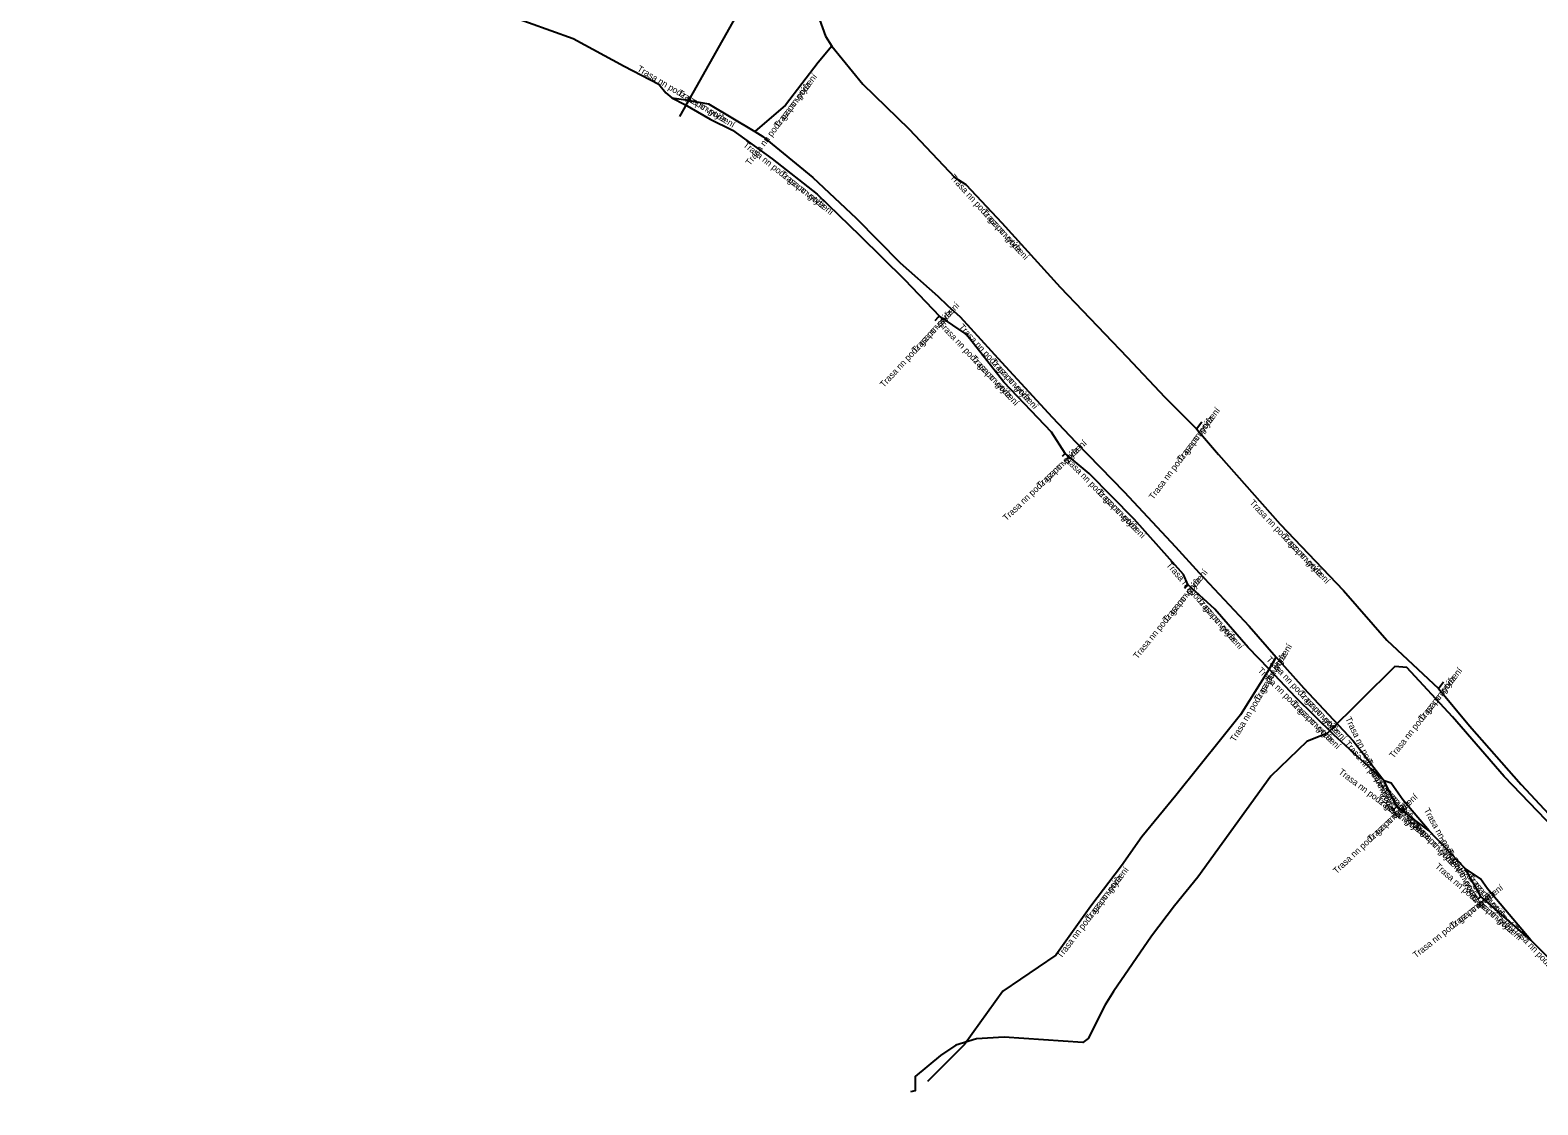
# Model space of a CAD drawing. Extents: x -703240 to -702678, y -1007635 to -1007322.
# Drawn here: x -703170.5 to -703052.5, y -1007557.6 to -1007473.5 of the extents above; entities that cross this region are included whole.
import ezdxf

# ---------------------------------------------------------------- set-up
doc = ezdxf.new("R2010")
doc.units = 0
for name, color, linetype in [('Popiskový text - Ostatní atributy Trasy', 7, 'Continuous'), ('Spojnice NN', 7, 'Continuous'), ('Spojnice VN', 7, 'Continuous')]:
    doc.layers.add(name, color=color, linetype=linetype)

msp = doc.modelspace()

# ---------------------------------------------------------------- linework, layer by layer
at = {"layer": 'Spojnice NN'}
for points in [[(-703105.19, -1007457.24), (-703106.16, -1007459.83), (-703107.31, -1007462.78), (-703109.11, -1007466.66), (-703109.74, -1007469.54), (-703109.29, -1007470.92), (-703108.22, -1007473.93), (-703107.73, -1007474.7)], [(-703105.19, -1007457.24), (-703106.16, -1007459.83), (-703107.31, -1007462.78), (-703109.11, -1007466.66), (-703109.74, -1007469.54), (-703109.29, -1007470.92), (-703108.22, -1007473.93), (-703107.73, -1007474.7)], [(-703170.48, -1007458.83), (-703167.59, -1007459.63), (-703164.52, -1007460.71), (-703160.1, -1007462.3), (-703155.58, -1007463.8), (-703150.53, -1007465.57), (-703146.69, -1007466.98), (-703141.78, -1007469.02), (-703136.93, -1007470.9), (-703131.46, -1007472.86), (-703127.97, -1007474.1), (-703123.99, -1007476.28), (-703121.27, -1007477.68), (-703120.71, -1007478.36), (-703120.24, -1007478.76)], [(-703170.48, -1007458.83), (-703167.59, -1007459.63), (-703164.52, -1007460.71), (-703160.1, -1007462.3), (-703155.58, -1007463.8), (-703150.53, -1007465.57), (-703146.69, -1007466.98), (-703141.78, -1007469.02), (-703136.93, -1007470.9), (-703131.46, -1007472.86), (-703127.97, -1007474.1), (-703123.99, -1007476.28), (-703121.27, -1007477.68), (-703120.71, -1007478.36), (-703120.24, -1007478.76)], [(-703107.73, -1007474.7), (-703108.8, -1007475.97), (-703111.34, -1007479.33), (-703113.75, -1007481.39)], [(-703107.73, -1007474.7), (-703108.8, -1007475.97), (-703111.34, -1007479.33), (-703113.75, -1007481.39)], [(-703107.73, -1007474.7), (-703105.3, -1007477.69), (-703101.7, -1007481.18), (-703098.1, -1007484.98), (-703097.23, -1007485.53), (-703094.43, -1007488.53), (-703089.86, -1007493.56), (-703084.61, -1007499.04), (-703081.67, -1007502.19), (-703079.19, -1007504.66)], [(-703107.73, -1007474.7), (-703105.3, -1007477.69), (-703101.7, -1007481.18), (-703098.1, -1007484.98), (-703097.23, -1007485.53), (-703094.43, -1007488.53), (-703089.86, -1007493.56), (-703084.61, -1007499.04), (-703081.67, -1007502.19), (-703079.19, -1007504.66)], [(-703120.24, -1007478.76), (-703119.33, -1007478.88), (-703117.38, -1007479.22), (-703113.75, -1007481.39)], [(-703120.24, -1007478.76), (-703119.24, -1007479.28), (-703117.25, -1007480.43), (-703115.5, -1007481.27), (-703112.39, -1007483.52), (-703108.87, -1007486.3), (-703105.53, -1007489.53), (-703102.01, -1007493), (-703099.3, -1007495.83)], [(-703120.24, -1007478.76), (-703119.33, -1007478.88), (-703117.38, -1007479.22), (-703113.75, -1007481.39)], [(-703120.24, -1007478.76), (-703119.24, -1007479.28), (-703117.25, -1007480.43), (-703115.5, -1007481.27), (-703112.39, -1007483.52), (-703108.87, -1007486.3), (-703105.53, -1007489.53), (-703102.01, -1007493), (-703099.3, -1007495.83)], [(-703113.75, -1007481.39), (-703113.13, -1007481.77), (-703109.22, -1007484.98), (-703105.81, -1007488.17), (-703102.37, -1007491.67), (-703099.42, -1007494.27), (-703098.67, -1007495), (-703097.68, -1007495.9), (-703094.44, -1007499.44), (-703090.48, -1007503.74), (-703088.62, -1007505.7), (-703084.85, -1007509.58), (-703080.82, -1007513.88), (-703078.98, -1007515.94), (-703075.05, -1007520.11), (-703072.95, -1007522.53)], [(-703113.75, -1007481.39), (-703113.13, -1007481.77), (-703109.22, -1007484.98), (-703105.81, -1007488.17), (-703102.37, -1007491.67), (-703099.42, -1007494.27), (-703098.67, -1007495), (-703097.68, -1007495.9), (-703094.44, -1007499.44), (-703090.48, -1007503.74), (-703088.62, -1007505.7), (-703084.85, -1007509.58), (-703080.82, -1007513.88), (-703078.98, -1007515.94), (-703075.05, -1007520.11), (-703072.95, -1007522.53)], [(-703099.3, -1007495.83), (-703099.4, -1007495.92), (-703099.66, -1007496.2)], [(-703099.3, -1007495.83), (-703099.4, -1007495.92), (-703099.66, -1007496.2)], [(-703089.46, -1007506.59), (-703090.54, -1007504.93), (-703094.25, -1007501.01), (-703097.2, -1007497.24), (-703099.3, -1007495.83)], [(-703089.46, -1007506.59), (-703090.54, -1007504.93), (-703094.25, -1007501.01), (-703097.2, -1007497.24), (-703099.3, -1007495.83)], [(-703079.19, -1007504.66), (-703078.77, -1007504.1)], [(-703079.19, -1007504.66), (-703078.77, -1007504.1)], [(-703079.19, -1007504.66), (-703077.45, -1007506.67), (-703072.62, -1007512.11), (-703067.67, -1007517.31), (-703064.27, -1007521.2), (-703060.24, -1007524.97)], [(-703079.19, -1007504.66), (-703077.45, -1007506.67), (-703072.62, -1007512.11), (-703067.67, -1007517.31), (-703064.27, -1007521.2), (-703060.24, -1007524.97)], [(-703089.46, -1007506.59), (-703089.7, -1007506.82)], [(-703089.46, -1007506.59), (-703089.7, -1007506.82)], [(-703079.87, -1007516.84), (-703080.2, -1007516.06), (-703084.05, -1007511.74), (-703087.58, -1007508.16), (-703089.46, -1007506.59)], [(-703079.87, -1007516.84), (-703080.2, -1007516.06), (-703084.05, -1007511.74), (-703087.58, -1007508.16), (-703089.46, -1007506.59)], [(-703079.87, -1007516.84), (-703080.13, -1007517.16)], [(-703079.87, -1007516.84), (-703080.13, -1007517.16)], [(-703073.5, -1007523.46), (-703075.14, -1007521.78), (-703077.75, -1007518.77), (-703079.87, -1007516.84)], [(-703073.5, -1007523.46), (-703075.14, -1007521.78), (-703077.75, -1007518.77), (-703079.87, -1007516.84)], [(-703073.5, -1007523.46), (-703072.95, -1007522.53)], [(-703073.5, -1007523.46), (-703072.95, -1007522.53)], [(-703072.95, -1007522.53), (-703070.78, -1007524.95), (-703066.91, -1007529.07), (-703064.48, -1007532.21)], [(-703072.95, -1007522.53), (-703070.78, -1007524.95), (-703066.91, -1007529.07), (-703064.48, -1007532.21)], [(-703073.5, -1007523.46), (-703075.73, -1007527.03), (-703077.2, -1007528.88), (-703080.81, -1007533.35), (-703083.45, -1007536.6), (-703085.05, -1007538.87), (-703087.44, -1007542.01), (-703090.19, -1007545.86), (-703094.33, -1007548.68), (-703097.35, -1007552.84), (-703100.24, -1007555.74)], [(-703073.5, -1007523.46), (-703075.73, -1007527.03), (-703077.2, -1007528.88), (-703080.81, -1007533.35), (-703083.45, -1007536.6), (-703085.05, -1007538.87), (-703087.44, -1007542.01), (-703090.19, -1007545.86), (-703094.33, -1007548.68), (-703097.35, -1007552.84), (-703100.24, -1007555.74)], [(-703064.48, -1007532.21), (-703068.44, -1007528.61), (-703071.41, -1007525.68), (-703073.5, -1007523.46)], [(-703064.48, -1007532.21), (-703068.44, -1007528.61), (-703071.41, -1007525.68), (-703073.5, -1007523.46)], [(-703060.24, -1007524.97), (-703059.84, -1007524.46)], [(-703060.24, -1007524.97), (-703059.84, -1007524.46)], [(-703060.24, -1007524.97), (-703057.82, -1007527.9), (-703053.76, -1007532.5), (-703049.79, -1007536.76), (-703045.88, -1007540.85), (-703042.43, -1007544.47), (-703037.97, -1007549.38), (-703033.75, -1007553.9), (-703030.23, -1007557.57)], [(-703060.24, -1007524.97), (-703057.82, -1007527.9), (-703053.76, -1007532.5), (-703049.79, -1007536.76), (-703045.88, -1007540.85), (-703042.43, -1007544.47), (-703037.97, -1007549.38), (-703033.75, -1007553.9), (-703030.23, -1007557.57)], [(-703060.96, -1007536.12), (-703063.03, -1007533.7), (-703063.95, -1007532.39), (-703064.48, -1007532.21)], [(-703063.51, -1007534.22), (-703064.48, -1007532.21)], [(-703063.51, -1007534.22), (-703064.48, -1007532.21)], [(-703060.96, -1007536.12), (-703063.03, -1007533.7), (-703063.95, -1007532.39), (-703064.48, -1007532.21)], [(-703063.51, -1007534.22), (-703063.84, -1007534.53)], [(-703063.51, -1007534.22), (-703063.84, -1007534.53)], [(-703060.96, -1007536.12), (-703063.51, -1007534.22)], [(-703060.96, -1007536.12), (-703063.51, -1007534.22)], [(-703058.14, -1007539.07), (-703060.96, -1007536.12)], [(-703058.14, -1007539.07), (-703060.96, -1007536.12)], [(-703053.01, -1007544.68), (-703056.39, -1007540.67), (-703056.95, -1007539.89), (-703058.14, -1007539.07)], [(-703056.93, -1007541.26), (-703058.14, -1007539.07)], [(-703056.93, -1007541.26), (-703058.14, -1007539.07)], [(-703053.01, -1007544.68), (-703056.39, -1007540.67), (-703056.95, -1007539.89), (-703058.14, -1007539.07)], [(-703056.93, -1007541.26), (-703057.17, -1007541.45)], [(-703056.93, -1007541.26), (-703057.17, -1007541.45)], [(-703053.01, -1007544.68), (-703056.93, -1007541.26)], [(-703053.01, -1007544.68), (-703056.93, -1007541.26)], [(-703045.83, -1007551.96), (-703046.67, -1007551.19), (-703050.31, -1007547.33), (-703053.01, -1007544.68)], [(-703045.83, -1007551.96), (-703046.67, -1007551.19), (-703050.31, -1007547.33), (-703053.01, -1007544.68)]]:
    msp.add_lwpolyline(points, dxfattribs=at)
at = {"layer": 'Spojnice VN'}
for points in [[(-703119.62, -1007480.22), (-703093.28, -1007433.41)], [(-703051.16, -1007535.96), (-703055.1, -1007531.88), (-703059.13, -1007527.2), (-703062.71, -1007523.35), (-703063.65, -1007523.26), (-703068.93, -1007528.49), (-703070.55, -1007529.14), (-703073.37, -1007531.84), (-703079.07, -1007539.75), (-703080.91, -1007541.98), (-703082.69, -1007544.38), (-703085.67, -1007548.69), (-703086.34, -1007549.73), (-703087.66, -1007552.38), (-703088.08, -1007552.7), (-703094.24, -1007552.28), (-703096.41, -1007552.41), (-703098.03, -1007552.89), (-703099.23, -1007553.71), (-703101.19, -1007555.36), (-703101.2, -1007556.48), (-703101.57, -1007556.55)]]:
    msp.add_lwpolyline(points, dxfattribs=at)

# ---------------------------------------------------------------- texts
at = {"layer": 'Popiskový text - Ostatní atributy Trasy'}
for s, rotation, p in [('Trasa nn podz gz po vytýèení', 329.1292, (-703123.01, -1007476.61)), ('Trasa nn podz gz po vytýèení', 52.9125, (-703114.13, -1007484.09)), ('Trasa nn podz', 329.1292, (-703119.84, -1007478.5)), ('Trasa nn podz', 52.9125, (-703111.9, -1007481.15)), ('Trasa nn podz gz po vytýèení', 321.6993, (-703114.71, -1007482.52)), ('Trasa nn podz', 321.6993, (-703111.82, -1007484.8)), ('Trasa nn podz gz po vytýèení', 312.2567, (-703098.51, -1007485)), ('Trasa nn podz', 312.2567, (-703096.03, -1007487.73)), ('Trasa nn podz gz po vytýèení', 47.1211, (-703103.66, -1007501.46)), ('Trasa nn podz', 47.1211, (-703101.15, -1007498.76)), ('Trasa nn podz gz po vytýèení', 313.4234, (-703099.4, -1007496.52)), ('Trasa nn podz gz po vytýèení', 312.6429, (-703097.83, -1007496.72)), ('Trasa nn podz', 313.4234, (-703096.86, -1007499.19)), ('Trasa nn podz', 312.6429, (-703095.33, -1007499.43)), ('Trasa nn podz gz po vytýèení', 53.1301, (-703082.56, -1007510.24)), ('Trasa nn podz', 53.1301, (-703080.35, -1007507.29)), ('Trasa nn podz gz po vytýèení', 43.7811, (-703094.06, -1007511.9)), ('Trasa nn podz', 43.7811, (-703091.4, -1007509.35)), ('Trasa nn podz gz po vytýèení', 314.5971, (-703089.61, -1007507.03)), ('Trasa nn podz', 314.5971, (-703087.02, -1007509.66)), ('Trasa nn podz gz po vytýèení', 313.5891, (-703075.07, -1007510.48)), ('Trasa nn podz', 313.5891, (-703072.53, -1007513.15)), ('Trasa nn podz gz po vytýèení', 50.9061, (-703083.8, -1007522.71)), ('Trasa nn podz gz po vytýèení', 310.9289, (-703081.58, -1007515.34)), ('Trasa nn podz', 50.9061, (-703081.48, -1007519.85)), ('Trasa nn podz', 310.9289, (-703079.17, -1007518.13)), ('Trasa nn podz gz po vytýèení', 59.1907, (-703076.16, -1007529.2)), ('Trasa nn podz', 59.1907, (-703074.28, -1007526.03)), ('Trasa nn podz gz po vytýèení', 313.2079, (-703073.75, -1007522.74)), ('Trasa nn podz gz po vytýèení', 315.3884, (-703074.43, -1007523.62)), ('Trasa nn podz gz po vytýèení', 51.8924, (-703063.75, -1007530.49)), ('Trasa nn podz', 51.8924, (-703061.47, -1007527.59)), ('Trasa nn podz', 313.2079, (-703071.23, -1007525.42)), ('Trasa nn podz', 315.3884, (-703071.8, -1007526.21)), ('Trasa nn podz gz po vytýèení', 295.7614, (-703067.55, -1007527.34)), ('Trasa nn podz gz po vytýèení', 310.5427, (-703067.63, -1007529.32)), ('Trasa nn podz gz po vytýèení', 323.3103, (-703068.1, -1007531.61)), ('Trasa nn podz', 295.7614, (-703065.95, -1007530.66)), ('Trasa nn podz', 310.5427, (-703065.24, -1007532.12)), ('Trasa nn podz gz po vytýèení', 43.2101, (-703068.21, -1007539.53)), ('Trasa nn podz', 43.2101, (-703065.52, -1007537)), ('Trasa nn podz', 323.3103, (-703065.15, -1007533.81)), ('Trasa nn podz gz po vytýèení', 313.7093, (-703064.74, -1007533.1)), ('Trasa nn podz gz po vytýèení', 298.9212, (-703061.41, -1007534.5)), ('Trasa nn podz', 313.7093, (-703062.19, -1007535.77)), ('Trasa nn podz gz po vytýèení', 310.1273, (-703060.38, -1007536.95)), ('Trasa nn podz', 298.9212, (-703059.63, -1007537.72)), ('Trasa nn podz gz po vytýèení', 52.7236, (-703089.77, -1007546.15)), ('Trasa nn podz', 52.7236, (-703087.54, -1007543.22)), ('Trasa nn podz gz po vytýèení', 318.897, (-703060.55, -1007538.97)), ('Trasa nn podz', 310.1273, (-703058, -1007539.77)), ('Trasa nn podz gz po vytýèení', 38.3675, (-703062, -1007546.11)), ('Trasa nn podz', 38.3675, (-703059.11, -1007543.82)), ('Trasa nn podz', 318.897, (-703057.77, -1007541.39)), ('Trasa nn podz gz po vytýèení', 313.3198, (-703054.56, -1007543.77))]:
    msp.add_text(s, height=0.5, rotation=rotation, dxfattribs=at).set_placement(p)

doc.saveas('drawing.dxf')
